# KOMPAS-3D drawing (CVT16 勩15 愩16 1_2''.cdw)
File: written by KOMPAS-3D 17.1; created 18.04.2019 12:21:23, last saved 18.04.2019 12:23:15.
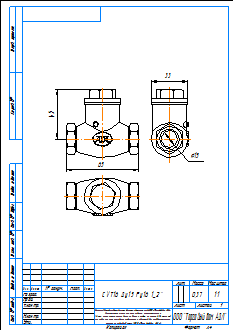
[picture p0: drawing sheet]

Sheet 1: A4, portrait

Title block, sheet 1: name: CVT16 Ду15 Ру16 1_2''; material: Внимание! Данный продукт является объектом авторского права ООО «Торговый Дом АДЛ». / Запрещается изменение, копирование, распространение / (в том числе путем копирования на другие сайты и ресурсы в Интернете) / или любое иное использование информации и объектов без предварительного / согласия правообладателя (ООО «Торговый Дом АДЛ»).; mass: 0,37; sheets: 1; organisation: ООО "Торговый дом АДЛ"; sheet format: A4; stored path: \\adlc.lan\data\АДЛ_ПКД\3D-модели\ADL production\Клапаны обратные ГРАНЛОК\CVT16 Затвор обратный поворотный резьбовой\KOMPAS 2D\CVT16 Ду15 Ру16 1_2''.cdw

Views: Вид 1, Проекционный вид 2, Проекционный вид 3
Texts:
  user
Dimensions and other numbers on the sheet: 65; 45; 15; 33; 1:1; 1; 0,37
